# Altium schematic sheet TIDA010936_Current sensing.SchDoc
size 431 x 279 mm; Date: Not shown in title block; ApprovedBy: Not shown in title block; CheckedBy: Not shown in title block; Author: Not shown in title block; CompanyName: Not shown in title block; Engineer: Not shown in title block; Organization: Not shown in title block; Address1: Not shown in title block; Address2: Not shown in title block; Address3: Not shown in title block; Address4: Not shown in title block; DocumentNumber: 2; Revision: Use project parameter SCH_Rev; SheetNumber: 2; SheetTotal: 3; PageSetup: Record=PageOptions¦CenterHorizontal=True¦CenterVertical=True¦PrintScale=1.00¦XCorrection=1.00¦YCorrection=1.00¦PrintKind=0¦BorderSize=5000000¦LeftOffset=0¦BottomOffset=0¦Orientation=2¦PaperLength=1000¦PaperWidth=1000¦Scale=100¦PaperSource=15¦PrintQuality=600¦MediaType=1¦DitherType=10¦PaperKind=Letter¦PrintScaleMode=1
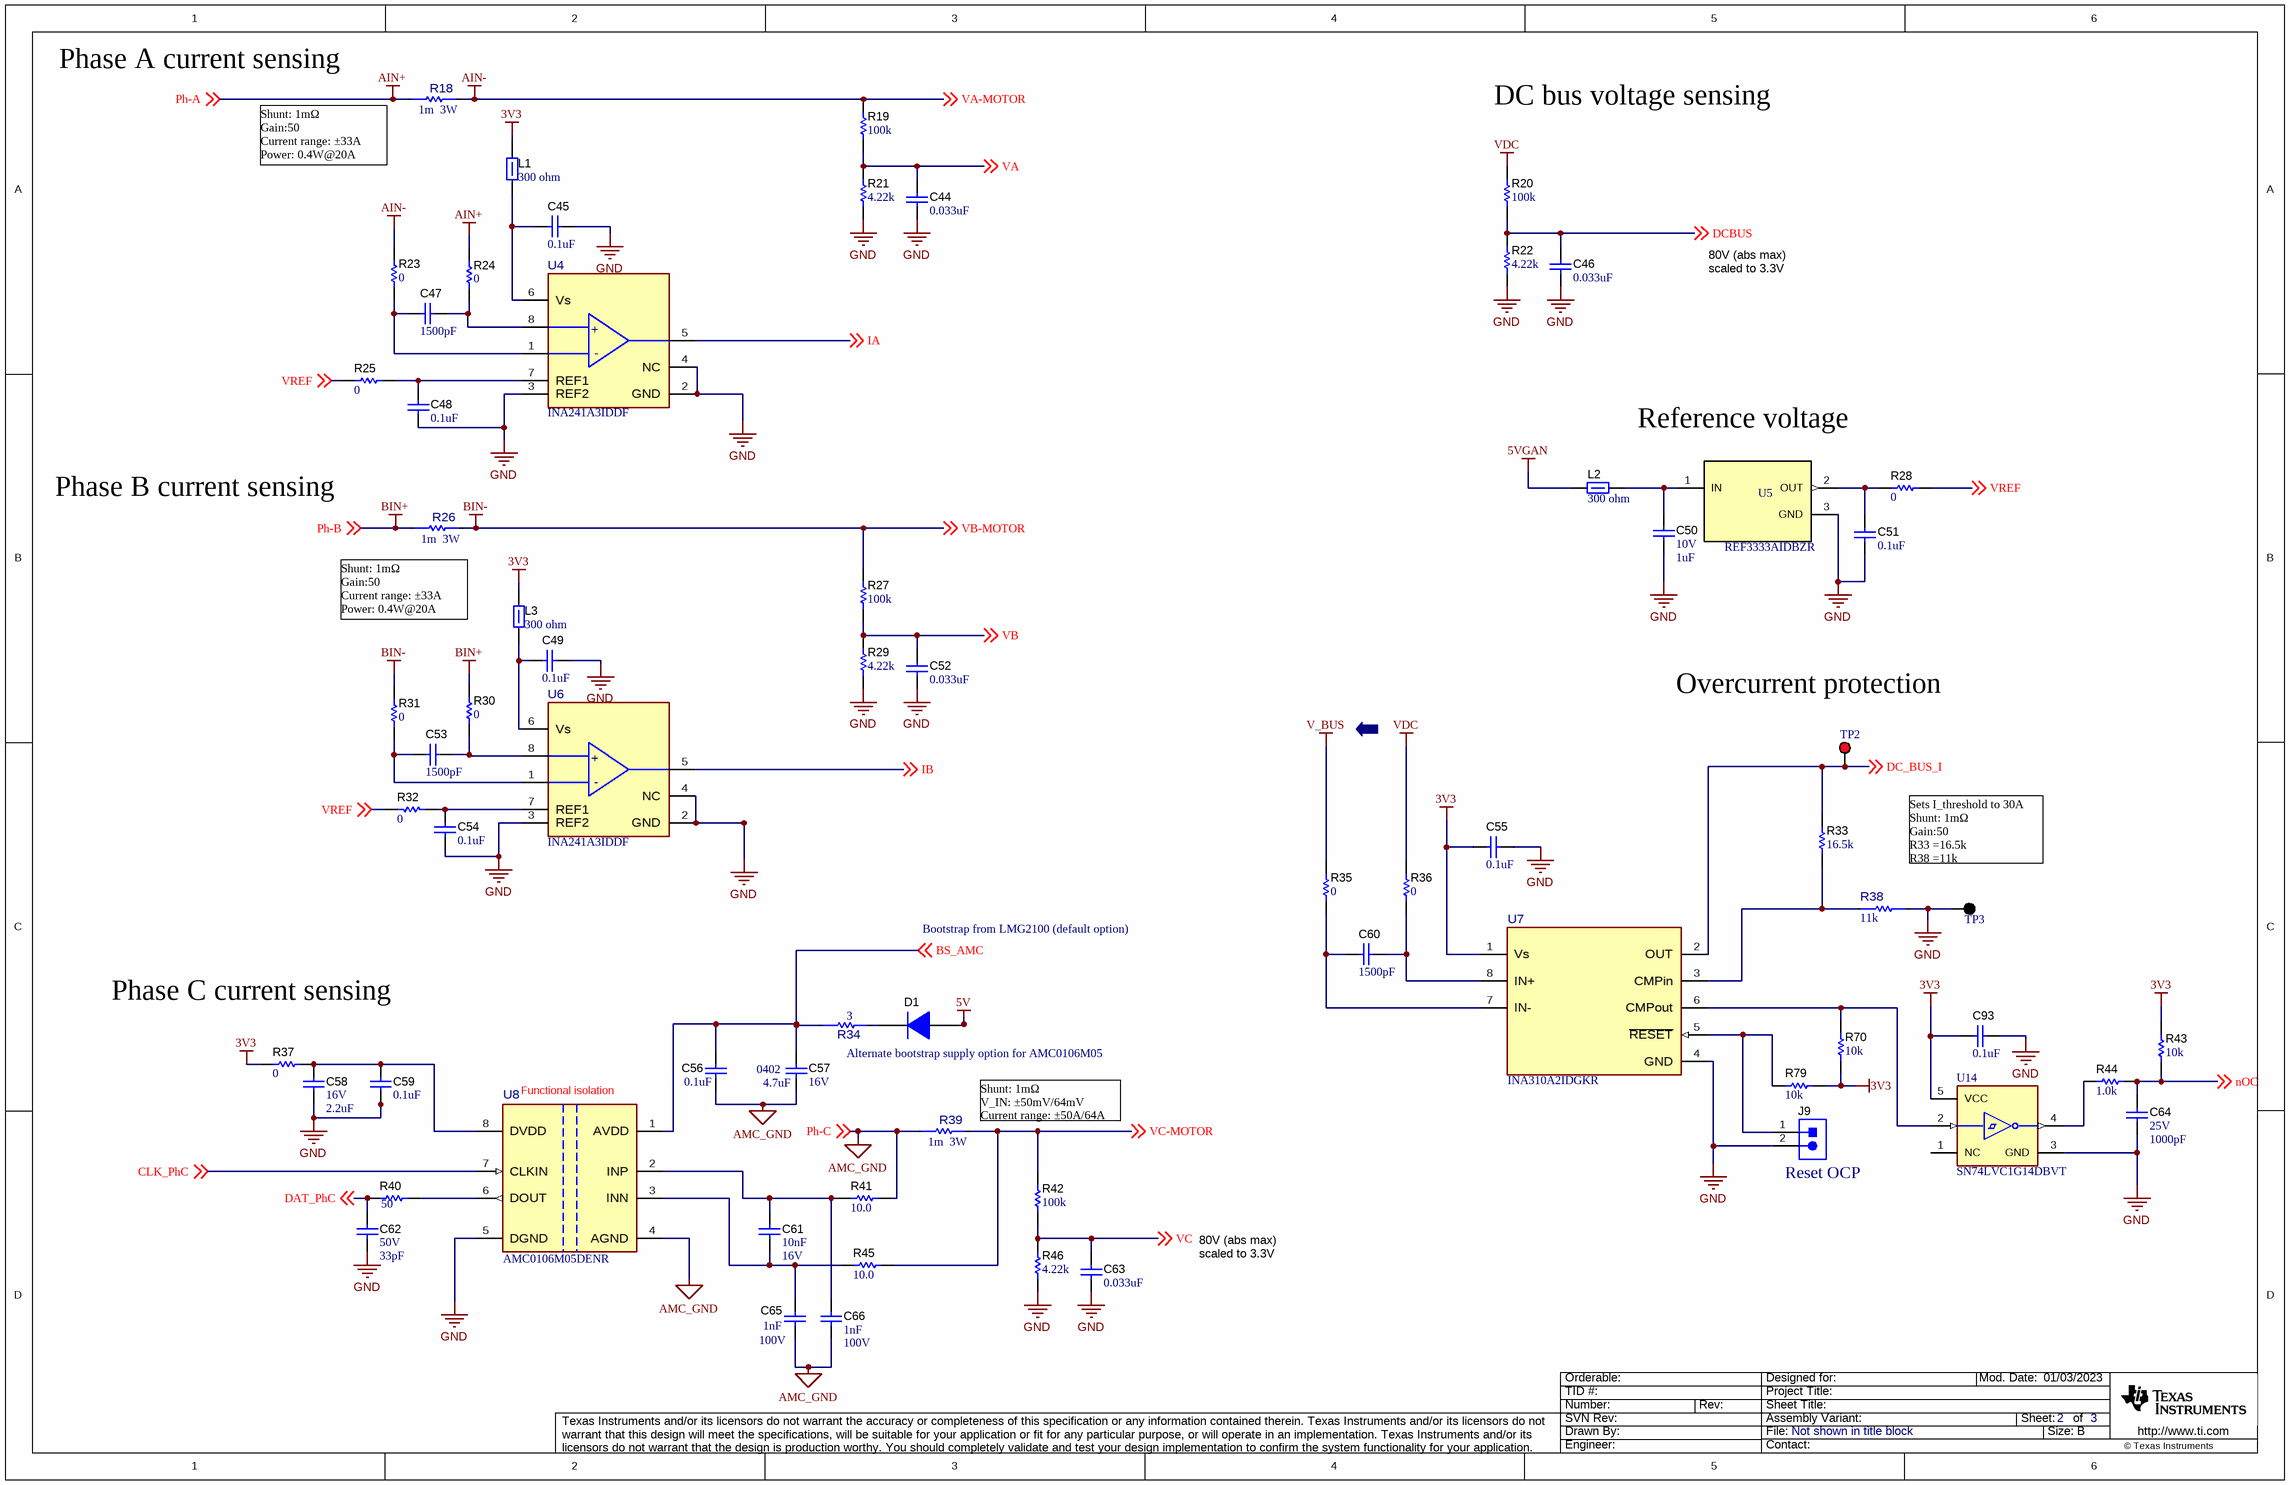
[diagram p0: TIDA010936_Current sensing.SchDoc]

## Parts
C44  ValueDisplayed: 0.033uF  [0402]  (hidden comment: CMP-0006632-2)
C45  ValueDisplayed: 0.1uF  [0402]  (hidden comment: CMP-0006351-2)
C46  ValueDisplayed: 0.033uF  [0402]  (hidden comment: CMP-0006632-2)
C47  ValueDisplayed: 1500pF  [0402]  (hidden comment: CMP-0006245-2)
C48  ValueDisplayed: 0.1uF  [0603]  (hidden comment: CMP-0007378-5)
C49  ValueDisplayed: 0.1uF  [0402]  (hidden comment: CMP-0006351-2)
C50  VDC_V: 10V  ValueDisplayed: 1uF  [0603]  (hidden comment: GRM188R61A105KA61D)
C51  ValueDisplayed: 0.1uF  [0603]  (hidden comment: CMP-0007378-5)
C52  ValueDisplayed: 0.033uF  [0402]  (hidden comment: CMP-0006632-2)
C53  ValueDisplayed: 1500pF  [0402]  (hidden comment: CMP-0006245-2)
C54  ValueDisplayed: 0.1uF  [0603]  (hidden comment: CMP-0007378-5)
C55  ValueDisplayed: 0.1uF  [0402]  (hidden comment: CMP-0006351-2)
C56  ValueDisplayed: 0.1uF  [0402]  (hidden comment: CMP-0006351-2)
C57  PackageReference: 0402  VDC_V: 16V  ValueDisplayed: 4.7uF  [0402_070]  (hidden comment: GRM155D81C475ME15D)
C58  VDC_V: 16V  ValueDisplayed: 2.2uF  [0402]  (hidden comment: GRM155R61C225KE11D)
C59  ValueDisplayed: 0.1uF  [0402]  (hidden comment: CMP-0006351-2)
C60  ValueDisplayed: 1500pF  [0402]  (hidden comment: CMP-0006245-2)
C61  Cap_F: 10nF  VDC_V: 16V  [0603]  (hidden comment: 885012206040)
C62  VDC_V: 50V  ValueDisplayed: 33pF  [0603]  (hidden comment: C0603C330J5GACTU)
C63  ValueDisplayed: 0.033uF  [0402]  (hidden comment: CMP-0006632-2)
C64  VDC_V: 25V  ValueDisplayed: 1000pF  [0603]  (hidden comment: C0603C102F3GACTU)
C65  Cap_F: 1nF  VDC_V: 100V  [0603]  (hidden comment: 06031C102JAT2A)
C66  Cap_F: 1nF  VDC_V: 100V  [0603]  (hidden comment: 06031C102JAT2A)
C93  ValueDisplayed: 0.1uF  [0402]  (hidden comment: CMP-0006351-2)
D1  ES1C-13-F;  Superfast Rectifier, 150 V, 1 A  [SMA]  (value not drawn)
J9  (no value)  [CONN_PEC02SAAN]
L1  value 300 ohm  [0402]  (hidden comment: CMP-0003227-1)
L2  value 300 ohm  [0402]  (hidden comment: CMP-0003227-1)
L3  value 300 ohm  [0402]  (hidden comment: CMP-0003227-1)
R18  value 1m  Power_W: 3W  [FP-ULRG32512R001FLFSLT_2512-MFG]  (hidden comment: ULRG32512R001FLFSLT)
R19  ValueDisplayed: 100k  [0402]  (hidden comment: CMP-0025950-3)
R20  ValueDisplayed: 100k  [0402]  (hidden comment: CMP-0025950-3)
R21  ValueDisplayed: 4.22k  [0402]  (hidden comment: CMP-0026407-2)
R22  ValueDisplayed: 4.22k  [0402]  (hidden comment: CMP-0026407-2)
R23  ValueDisplayed: 0  [0402]  (hidden comment: CMP-0026822-3)
R24  ValueDisplayed: 0  [0402]  (hidden comment: CMP-0026822-3)
R25  ValueDisplayed: 0  [0402]  (hidden comment: CMP-0026822-3)
R26  value 1m  Power_W: 3W  [FP-ULRG32512R001FLFSLT_2512-MFG]  (hidden comment: ULRG32512R001FLFSLT)
R27  ValueDisplayed: 100k  [0402]  (hidden comment: CMP-0025950-3)
R28  ValueDisplayed: 0  [0402]  (hidden comment: CMP-0026822-3)
R29  ValueDisplayed: 4.22k  [0402]  (hidden comment: CMP-0026407-2)
R30  ValueDisplayed: 0  [0402]  (hidden comment: CMP-0026822-3)
R31  ValueDisplayed: 0  [0402]  (hidden comment: CMP-0026822-3)
R32  ValueDisplayed: 0  [0402]  (hidden comment: CMP-0026822-3)
R33  ValueDisplayed: 16.5k  [0402]  (hidden comment: CRCW040216K5FKED)
R34  value 3  [FP-CRCW06033R00FKEAHP_0603-MFG]  (hidden comment: CRCW06033R00FKEAHP)
R35  ValueDisplayed: 0  [0402]  (hidden comment: CMP-0026822-3)
R36  ValueDisplayed: 0  [0402]  (hidden comment: CMP-0026822-3)
R37  ValueDisplayed: 0  [0402]  (hidden comment: CMP-0026822-3)
R38  value 11k  [FP-RMCF0402FT11K0_0402-MFG]  (hidden comment: RMCF0402FT11K0)
R39  value 1m  Power_W: 3W  [FP-ULRG32512R001FLFSLT_2512-MFG]  (hidden comment: ULRG32512R001FLFSLT)
R40  ValueDisplayed: 50  [0603]  (hidden comment: CRCW060350R0FKEA)
R41  ValueDisplayed: 10.0  [0603]  (hidden comment: CRCW060310R0FKEAHP)
R42  ValueDisplayed: 100k  [0402]  (hidden comment: CMP-0025950-3)
R43  ValueDisplayed: 10k  [0402]  (hidden comment: CMP-0026825-5)
R44  ValueDisplayed: 1.0k  [0603]  (hidden comment: RC0603JR-071KL)
R45  ValueDisplayed: 10.0  [0603]  (hidden comment: CRCW060310R0FKEAHP)
R46  ValueDisplayed: 4.22k  [0402]  (hidden comment: CMP-0026407-2)
R70  ValueDisplayed: 10k  [0402]  (hidden comment: CMP-0026825-5)
R79  ValueDisplayed: 10k  [0402]  (hidden comment: CMP-0026825-5)
TP2  5000  [Keystone5000]  (value not drawn)
TP3  CMP-0055138-2  [Keystone5001]  (value not drawn)
U4  INA241A3IDDF  [DDF0008A-MFG]
U5  REF3333AIDBZR  [DBZ0003A_N]
U6  INA241A3IDDF  [DDF0008A-MFG]
U7  INA310A2IDGKR  [DGK0008A-MFG]
U8  AMC0106M05DENR  [DEN0008A-MFG-NO_VIA]
U14  SN74LVC1G14DBVT  [FP-DBV0005A-MFG]

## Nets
3V3: C55.2 C93.1 L1.1 L3.1 R37.2 R43.2 R70.2 R79.1 U7.1(Vs) U14.5(VCC)
5V: D1.2(A)
5VGAN: L2.2
AIN+: R18.1 R24.2 ; off-sheet Ph-A  [also labelled Ph-A]
AIN-: R18.2 R19.2 R23.2 ; off-sheet VA-MOTOR  [also labelled VA-MOTOR]
AMC_GND: C56.2 C57.2 C65.2 C66.2 R39.1 R41.2 U8.4(AGND) ; off-sheet Ph-C  [also labelled Ph-C]
BIN+: R26.1 R30.2 ; off-sheet Ph-B  [also labelled Ph-B]
BIN-: R26.2 R27.2 R31.2 ; off-sheet VB-MOTOR  [also labelled VB-MOTOR]
GND: C44.2 C45.1 C46.2 C48.1 C49.1 C50.2 C51.1 C52.2 C54.1 C55.1 C58.2 C59.2 C62.2 C63.2 C64.2 C93.2 J9.2 R21.1 R22.1 R29.1 R38.2 R46.1 TP3.1 U4.2(GND) U4.3(REF2) U4.4(NC) U5.3(GND) U6.2(GND) U6.3(REF2) U6.4(NC) U7.4(GND) U8.5(DGND) U14.3(GND)
V_BUS: R35.2
VDC: R20.2 R36.2
BS_AMC: C56.1 C57.1 R34.1 U8.1(AVDD) ; off-sheet BS_AMC
CLK_PhC: U8.7(CLKIN) ; off-sheet CLK_PhC
DAT_PhC: C62.1 R40.1 ; off-sheet DAT_PhC
DC_BUS_I: R33.2 TP2.1 U7.2(OUT) ; off-sheet DC_BUS_I
DCBUS: C46.1 R20.1 R22.2 ; off-sheet DCBUS
IA: U4.5(OUT) ; off-sheet IA
IB: U6.5(OUT) ; off-sheet IB
nOC: C64.1 R43.1 R44.2 ; off-sheet nOC
VA: C44.1 R19.1 R21.2 ; off-sheet VA
VB: C52.1 R27.1 R29.2 ; off-sheet VB
VC: C63.1 R42.1 R46.2 ; off-sheet VC
VC-MOTOR: R39.2 R42.2 R45.2 ; off-sheet VC-MOTOR
VREF: R25.1 R28.2 R32.2 ; off-sheet VREF
NetC45_2: C45.2 L1.2 U4.6(Vs)
NetC47_1: C47.1 R23.1 U4.1(IN-)
NetC47_2: C47.2 R24.1 U4.8(IN+)
NetC48_2: C48.2 R25.2 U4.7(REF1)
NetC49_2: C49.2 L3.2 U6.6(Vs)
NetC50_1: C50.1 L2.1 U5.1(IN)
NetC51_2: C51.2 R28.1 U5.2(OUT)
NetC53_1: C53.1 R31.1 U6.1(IN-)
NetC53_2: C53.2 R30.1 U6.8(IN+)
NetC54_2: C54.2 R32.1 U6.7(REF1)
NetC58_1: C58.1 C59.1 R37.1 U8.8(DVDD)
NetC60_1: C60.1 R35.1 U7.7(IN-)
NetC60_2: C60.2 R36.1 U7.8(IN+)
NetC61_1: C61.1 C66.1 R41.1 U8.2(INP)
NetC61_2: C61.2 C65.1 R45.1 U8.3(INN)
NetD1_1: D1.1(K) R34.2
NetJ9_1: J9.1 R79.2 U7.5(~{RESET})
NetR33_1: R33.1 R38.1 U7.3(CMPin)
NetR40_2: R40.2 U8.6(DOUT)
NetR44_1: R44.1 U14.4(Y)
NetR70_1: R70.1 U7.6(CMPout) U14.2(A)

Not connected (* = marked no-connect by the designer): U14 1(NC)

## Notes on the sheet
- (near R18) Phase A current sensing
- (near R18) Shunt: 1mΩ
  Gain:50
  Current range: ±33A
  Power: 0.4W@20A
- DC bus voltage sensing
- 80V (abs max) scaled to 3.3V
- Reference voltage
- (near R26) Phase B current sensing
- Shunt: 1mΩ
  Gain:50
  Current range: ±33A
  Power: 0.4W@20A
- (near TP2) Overcurrent protection
- ⬅
- Sets I_threshold to 30A
  Shunt: 1mΩ
  Gain:50
  R33 =16.5k
  R38 =11k
- Bootstrap from LMG2100 (default option)
- Phase C current sensing
- (near U8) Functional isolation
- Alternate bootstrap supply option for AMC0106M05
- (near R39) Shunt: 1mΩ
  V_IN: ±50mV/64mV
  Current range: ±50A/64A
- (near J9) Reset OCP

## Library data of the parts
C44 C46 C52 C63 = CMP-0006632-2: CAP, CERM, 0.033 uF, 10 V, +/- 10%, X7R, 0402; PartNumber: GRM155R71A333KA01D; Manufacturer: MuRata; Polarized: N; U/M: EA; Cap_F: 33nF; Value1: Unknown; VDC_V: 10V; TaMin_C: -55°C; TaMax_C: 125°C; AEC Category: Q200; SizeArea_mm2: 0.5; SizeAreaWB_mm2: 3; SizeX_mm: 1; SizeZ_mm: 0.6
C45 C49 C55 C56 C59 C93 = CMP-0006351-2: CAP, CERM, 0.1 uF, 16 V, +/- 10%, X7R, 0402; PartNumber: GCM155R71C104KA55D; Manufacturer: MuRata; Polarized: N; Value: 0.1uF; U/M: EA; Cap_F: 100nF; Value1: Unknown; VDC_V: 16V; TaMin_C: -55°C; TaMax_C: 125°C; AEC Category: Q200; SizeAreaWB_mm2: 3; SizeZ_mm: 0.6; SizeX_mm: 1; SizeY_mm: 0.5
C47 C53 C60 = CMP-0006245-2: CAP, CERM, 1500 pF, 25 V, +/- 5%, C0G/NP0, 0402; PartNumber: C0402H152J3GAC7867; Manufacturer: Kemet; Polarized: N; Value: 1500pF; U/M: EA; Cap_F: 1.5nF; Value1: Unknown; VDC_V: 25V; TaMin_C: -55°C; TaMax_C: 200°C; AEC Category: Q200; SizeArea_mm2: 0.5; SizeAreaWB_mm2: 3; SizeX_mm: 1; SizeZ_mm: 0.6
C48 C51 C54 = CMP-0007378-5: CAP, CERM, 0.1 uF, 16 V, +/- 10%, X7R, 0603; PartNumber: GRM188R71C104KA01D; Manufacturer: MuRata; Polarized: N; Value: 0.1uF; U/M: EA; Cap_F: 100nF; Value1: Unknown; VDC_V: 16V; TaMin_C: -55°C; TaMax_C: 125°C; SizeAreaWB_mm2: 4.68; SizeZ_mm: 1; SizeX_mm: 1.6; SizeY_mm: 0.8; SizeArea_mm2: 1.28; AEC Category: Q200
C50 = CMP-0007317-5: CAP, CERM, 1 uF, 10 V, +/- 10%, X5R, 0603; Manufacturer: MuRata; TaMin_C: -55°C; Polarized: N; SizeAreaWB_mm2: 4.68; Value1: Unknown; U/M: EA; Value: 1uF; TaMax_C: 85°C; SizeZ_mm: 1; SizeX_mm: 1.6; SizeY_mm: 0.8; SizeArea_mm2: 1.28; Cap_F: 1µF; AEC Category: Q200
C57 = CMP-0006527-2: CAP, CERM, 4.7 uF, 16 V, +/- 20%, X6T, 0402; Manufacturer: MuRata; TaMin_C: -55°C; Polarized: N; SizeAreaWB_mm2: 3; Value1: Unknown; U/M: EA; Value: 4.7uF; TaMax_C: 105°C; SizeZ_mm: 0.7; SizeX_mm: 1; SizeY_mm: 0.5; Cap_F: 4.7µF; AEC Category: Q200
C58 = CMP-0006594-2: CAP, CERM, 2.2 uF, 16 V, +/- 10%, X5R, 0402; Manufacturer: MuRata; TaMin_C: -55°C; Polarized: N; SizeAreaWB_mm2: 3; Value1: Unknown; U/M: EA; Value: 2.2uF; TaMax_C: 85°C; SizeZ_mm: 0.6; SizeX_mm: 1; SizeY_mm: 0.5; Cap_F: 2.2µF; AEC Category: Q200
C61 = CMP-0006828-4: CAP, CERM, 0.01 uF, 16 V, +/- 10%, X7R, 0603; Manufacturer: Wurth Elektronik; TaMin_C: -55°C; Polarized: N; SizeAreaWB_mm2: 4.68; Value1: Unknown; U/M: EA; Value: 0.01uF; TaMax_C: 125°C; SizeZ_mm: 1; SizeX_mm: 1.6; SizeY_mm: 0.8; SizeArea_mm2: 1.28; AEC Category: Q200
C62 = CMP-0006919-4: CAP, CERM, 33 pF, 50 V, +/- 5%, C0G/NP0, 0603; Manufacturer: Kemet; TaMin_C: -55°C; Polarized: N; SizeAreaWB_mm2: 4.68; Value1: Unknown; U/M: EA; Value: 33pF; TaMax_C: 125°C; SizeZ_mm: 1; SizeX_mm: 1.6; SizeY_mm: 0.8; SizeArea_mm2: 1.28; AEC Category: Q200
C64 = CMP-0080092-1: CAP, CERM, 1000 pF, 25 V,+/- 1%, C0G/NP0, 0603; Manufacturer: Kemet; Cap_F: 1nF; SizeAreaWB_mm2: 4.68; SizeArea_mm2: 1.28; AEC Qualified: N; AEC Category: Q200; Value: 1000pF; TaMax_C: 125°C; SizeZ_mm: 1; Green_REACh: Passed; TaMin_C: -55°C; SizeY_mm: 0.8; Green_Lifecycle: Active; U/M: EA; SizeX_mm: 1.6
C65 C66 = CMP-0006723-2: CAP, CERM, 1000 pF, 100 V, +/- 5%, X7R, 0603; Manufacturer: AVX; TaMin_C: -55°C; ESR_ohm: 0.276; Polarized: N; SizeAreaWB_mm2: 4.68; Value1: 0.276 ohm; U/M: EA; Value: 1000pF; TaMax_C: 125°C; SizeZ_mm: 1; SizeX_mm: 1.6; SizeY_mm: 0.8; SizeArea_mm2: 1.28; AEC Category: Q200
D1 = CMP-0029023-2: Diode, Superfast Rectifier, 150 V, 1 A, SMA; Manufacturer: Diodes Inc.; TJmax_C: 150°C; Vr_V: 150V; Value2: 0.92V; SizeX_mm: 5.59; Green_REACh: Incomplete; SizeAreaWB_mm2: 37.3428; Value: 150V; Vf_V: 920mV; Green_Lifecycle: Not Set; Value1: 1A; SizeZ_mm: 2.87; SizeArea_mm2: 16.3228; SizeY_mm: 2.92; AEC Category: Q101; RJC_CperW: 25
J9 = CMP-0002337-1: Header, 100mil, 2x1, Tin, TH; PartNumber: PEC02SAAN; Manufacturer: Sullins Connector Solutions; Pitch_mm: 2.54; Gender: Male; Shrouded: N; Row_Count: 1; Current_A: 3A; Voltage_V: 1.8kV; Cert_UL: Y; CNHeader: TRUE; Green_Lifecycle: Not Set; Green_REACh: Incomplete; CT: FALSE
L1-L3 = CMP-0003227-1: Ferrite Bead, 300 ohm @ 100 MHz, 0.2 A, 0402; PartNumber: 74279272; Manufacturer: Wurth Elektronik; Imax_A: 200mA; DCR_ohm: 0.8; Value1: 0.8 ohm; Value2: 0.2A; ZTyp@100MHz_Ohm: 300; Ztyp@1GHz_Ohm: 316.308; SizeAreaWB_mm2: 3; SizeZ_mm: 0.6; SizeX_mm: 1; SizeY_mm: 0.5
R18 R26 R39 = CMP-0042666-1: Res Metal Strip 2512 0.001 Ohm 1% 3W ±50ppm/C Pad SMD Automotive T/R; Manufacturer: TT Electronics; AEC Grade: Grade 0; AEC Qualified: Yes; SizeZ_mm: 0.8mm; TempCo: 50ppm/°C; TaMax_C: +170°C; TaMin_C: -55°C
R19 R20 R27 R42 = CMP-0025950-3: RES, 100 k, 1%, 0.063 W, AEC-Q200 Grade 0, 0402; PartNumber: CRCW0402100KFKED; Manufacturer: Vishay-Dale; Value: 100k; Power_W: 63mW; Value2: 0.063W; VDC_V: 50V; TempCo: 100 ppm/C; EIA_Code: E96; AEC Category: Q200; AEC Qualified: Y; AEC Grade: 0; SizeArea_mm2: 0.5; SizeX_mm: 1; SizeZ_mm: 0.6
R21 R22 R29 R46 = CMP-0026407-2: RES, 4.22 k, 1%, 0.063 W, AEC-Q200 Grade 0, 0402; PartNumber: CRCW04024K22FKED; Manufacturer: Vishay-Dale; Value: 4.22k; Value_Code: 4k22; Power_W: 63mW; Value2: 0.063W; VDC_V: 50V; TempCo: 100 ppm/C; EIA_Code: E96; AEC Category: Q200; AEC Qualified: Y; AEC Grade: 0; SizeArea_mm2: 0.5; SizeX_mm: 1; SizeZ_mm: 0.6
R23 R24 R30 R31 R35-R37 = CMP-0026822-3: RES, 0, 5%, 0.063 W, AEC-Q200 Grade 0, 0402; PartNumber: CRCW04020000Z0ED; Manufacturer: Vishay-Dale; Value: 0; Value_Code: 0000; Power_W: 63mW; Value2: 0.063W; VDC_V: 50V; TempCo: 200 ppm/C; SizeArea_mm2: 0.5; SizeX_mm: 1; SizeZ_mm: 0.6; EIA_Code: E24; AEC Category: Q200; AEC Qualified: Y
R25 R28 R32 = CMP-0026822-3: RES, 0, 5%, 0.063 W, AEC-Q200 Grade 0, 0402; PartNumber: CRCW04020000Z0ED; Manufacturer: Vishay-Dale; Value: 0; Value_Code: 0000; Power_W: 63mW; Value2: 0.063W; VDC_V: 50V; TempCo: 200 ppm/C; EIA_Code: E24; SizeX_mm: 1; SizeY_mm: 0.5; SizeZ_mm: 0.6; AEC Qualified: Y; AEC Category: Q200
R33 = CMP-0026041-3: RES, 16.5 k, 1%, 0.063 W, AEC-Q200 Grade 0, 0402; Manufacturer: Vishay-Dale; Power_W: 63mW; TempCo: 100 ppm/C; Value_Code: 16k5; Value: 16.5k; EIA_Code: E96; SizeX_mm: 1; SizeY_mm: 0.5; SizeZ_mm: 0.6; Value2: 0.063W; AEC Qualified: Y; VDC_V: 50V; AEC Category: Q200; AEC Grade: 0
R34 = CMP-0096630-1: RES Thick Film, 3Ω, 1%, 0.33W, 100ppm/°C, 0603; Manufacturer: Vishay; AEC Grade: Grade 0; VDC_V: 75V; AEC Qualified: Yes; Power_W: 330mW; SizeZ_mm: 0.55mm; Power: 250mW
R38 = CMP-0093921-1: 11 kOhms ±1% 0.063W, 1/16W Chip Resistor 0402 (1005 Metric) Automotive AEC-Q200 Thick Film; Manufacturer: Stackpole; VDC_V: 50V; AEC Qualified: Yes; SizeZ_mm: 0.4mm; AEC Grade: Grade 0; TempCo: 100ppm/°C; Power_W: 63mW
R40 = CMP-0022479-4: RES, 50, 1%, 0.1 W, AEC-Q200 Grade 0, 0603; Manufacturer: Vishay-Dale; Power_W: 100mW; TempCo: 100 ppm/C; Value_Code: 50R0; Value: 50; SizeX_mm: 1.6; SizeY_mm: 0.8; SizeZ_mm: 1; Value2: 0.1W; SizeArea_mm2: 1.28; AEC Qualified: Y; VDC_V: 75V; AEC Category: Q200; AEC Grade: 0
R41 R45 = CMP-0022004-2: RES, 10.0, 1%, 0.25 W, 0603; Manufacturer: Vishay-Dale; Power_W: 250mW; TempCo: 100 ppm/C; Value_Code: 10R0; U/M: EA; Value: 10.0; EIA_Code: E96; Res_ohm: 10; SizeX_mm: 1.6; SizeY_mm: 0.8; SizeZ_mm: 1; Value2: 0.25W; SizeArea_mm2: 1.28; VDC_V: 75V; AEC Category: Q200
R43 R70 R79 = CMP-0026825-5: RES, 10 k, 5%, 0.063 W, AEC-Q200 Grade 0, 0402; PartNumber: CRCW040210K0JNED; Manufacturer: Vishay-Dale; Value: 10k; Value_Code: 10k0; Power_W: 63mW; Value2: 0.063W; VDC_V: 50V; TempCo: 200 ppm/C; SizeArea_mm2: 0.5; SizeX_mm: 1; SizeZ_mm: 0.6; EIA_Code: E24; AEC Category: Q200; AEC Qualified: Y; AEC Grade: 0
R44 = CMP-0025899-5: RES, 1.0 k, 5%, 0.1 W, 0603; Manufacturer: Yageo; Power_W: 100mW; TempCo: 100 ppm/C; Value_Code: 1k00; Value: 1.0k; EIA_Code: E24; Res_ohm: 1k; SizeX_mm: 1.6; SizeY_mm: 0.8; SizeZ_mm: 1; Value2: 0.1W; SizeArea_mm2: 1.28; AEC Qualified: N; VDC_V: 75V; AEC Category: Q200; SizeAreaWB_mm2: 4.68
TP2 = CMP-0055137-1: Test Point, Miniature, Red, TH; Manufacturer: Keystone; CNHeader: FALSE; Green_Lifecycle: Active; Green_REACh: Passed; ContactFinish: Silver; CT: TRUE
TP3 = CMP-0055138-2: Test Point, Miniature, Black, TH; Manufacturer: Keystone Electronics; ContactFinish: Silver; CNHeader: FALSE; Green_Lifecycle: Active; Green_REACh: Passed; CT: TRUE
U4 U6 = CMP-0093649-2: -4-V to 110-V, Bidirectional, Ultra-Precise Current Sense Amplifier With Enhanced PWM Rejection; Manufacturer: Texas Instruments; Input Offset Voltage: 0.002mV; TaMax_C: +125°C; CompType: IC; Bandwidth: 1MHz; AEC Category: Q200; Response Time: 1.5us; TaMin_C: -40°C; Nominal Supply Current: 2.5mA; Number Of Channels: 1; TJmax_C: +150°C; Standoff Height: 0mm; SizeZ_mm: 1.1mm; Min Supply Voltage: 2.7V; Input Bias Current: 40uA; Voltage Gain: 0.05V/mV; AEC Qualified: No; Max Supply Voltage: 20V
U5 = CMP-0032556-1: 30 ppm / degC Drift, 3.9 uA Voltage Reference, -40 to 125 degC, 3-pin SOT-23 (DBZ), Green (RoHS & no Sb/Br); Manufacturer: Texas Instruments; Initial Accuracy @ 25/deg C(%): 0.15; Iout/Iz(Max)(mA): 5; Rating: Catalog; SubFamily: Series Voltage Reference; Temp Coeff(Max)(ppm/ degree C): 30; Temp Coeff(Typ)(ppm/ degree C): 8; VI(Max)(V): 5.5; VI(Min)(V): 3.5; VO(V): 3.3
U7 = CMP-0095220-1: -4V to 110V, 1.3-MHz, Ultra-Precise Current Sense Amplifier With OpenDrain Comparator and Reference; Manufacturer: Texas Instruments; Number Of Channels: 1; Nominal Supply Current: 1.5mA; Max Supply Voltage: 20V; Bandwidth: 1300kHz; Response Time: 10us; Min Supply Voltage: 2.7V; Input Bias Current: 20uA; TaMin_C: -40°C; Standoff Height: 0.05mm; TJmax_C: +150°C; TaMax_C: +125°C; SizeZ_mm: 1.1mm; AEC Qualified: No; Voltage Gain: 0.05V/mV; Input Offset Voltage: 0.015mV
U8 = CMP-0049066-2: ±50 mV Input Functionally Isolated Delta-Sigma Modulator for Current Sensing, VSON8; Manufacturer: Texas Instruments; Part Number: AMC0106DENR; SizeZ_mm: 1mm; Interface: SPI; Standoff Height: 0mm; AEC Category: Q200; CompType: IC
U14 = CMP-0859-00032-5: IC INVERTER SCHMITT 1CH SOT23-5; Manufacturer: Texas Instruments; Number Of Outputs: 1; Standoff Height: 0mm; Max Supply Voltage: 5.5V; Min Supply Voltage: 1.65V; Nominal Supply Current: 10uA; Max Junction Temp: +150°C; Logic Function Desc: Inverting; Propagation Delay: 6ns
